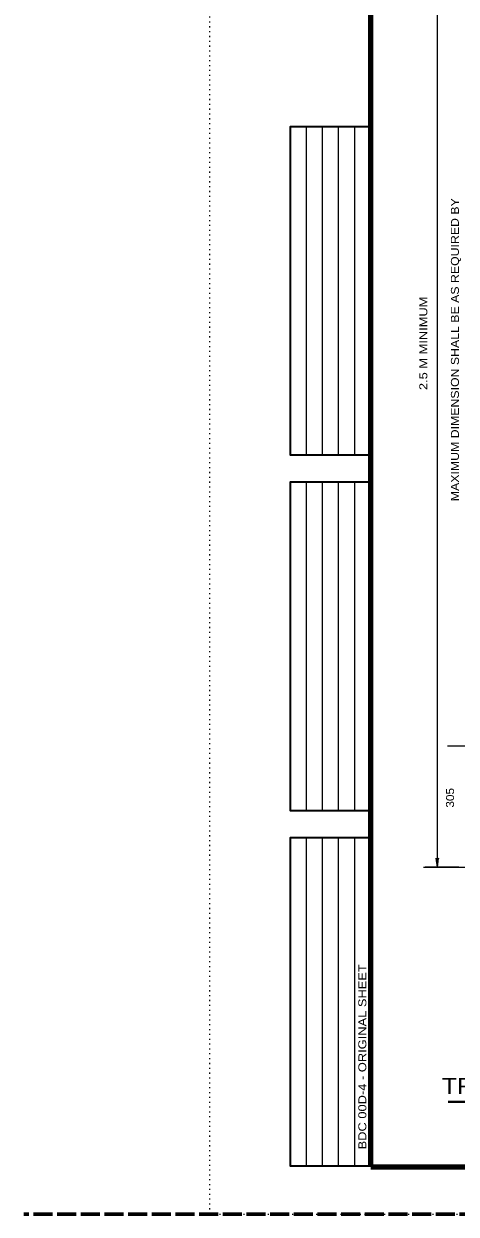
# Model space of a CAD drawing. Extents: x 312583 to 312854, y 144419 to 144597.
# Drawn here: x 312583.5 to 312624.6, y 144418.6 to 144531.6 of the extents above; entities that cross this region are included whole.
import ezdxf
from ezdxf.enums import TextEntityAlignment as Align

# ---------------------------------------------------------------- set-up
doc = ezdxf.new("R2010")
doc.units = 0
doc.header["$LTSCALE"] = 0.3
doc.linetypes.add('DOTTED', pattern=[1.5, 0.3, -1.2])
doc.linetypes.add('LONG_DASHED', pattern=[7.5, 6, -1.5])
for name, color, linetype, lineweight in [('1', 7, 'Continuous', 40), ('2', 7, 'Continuous', 13), ('62', 7, 'DOTTED', 13), ('63', 7, 'LONG_DASHED', 60)]:
    doc.layers.add(name, color=color, linetype=linetype, lineweight=lineweight)

msp = doc.modelspace()

# ---------------------------------------------------------------- linework, layer by layer
at = {"layer": '1', "lineweight": 25}
for p, q in [((312610.4087, 144490.6573), (312610.4087, 144521.8756)), ((312611.9315, 144490.6573), (312611.9315, 144521.8756)), ((312613.4543, 144490.6573), (312613.4543, 144521.8756)), ((312614.9772, 144490.6573), (312614.9772, 144521.8756)), ((312610.4087, 144456.901), (312610.4087, 144488.1192)), ((312611.9315, 144456.901), (312611.9315, 144488.1192)), ((312613.4543, 144456.901), (312613.4543, 144488.1192)), ((312614.9772, 144456.901), (312614.9772, 144488.1192)), ((312610.4087, 144423.1446), (312610.4087, 144454.3629)), ((312611.9315, 144423.1446), (312611.9315, 144454.3629)), ((312613.4543, 144423.1446), (312613.4543, 144454.3629)), ((312614.9772, 144423.1446), (312614.9772, 144454.3629))]:
    msp.add_line(p, q, dxfattribs=at)
at = {"layer": '1', "lineweight": 158}
msp.add_line((312616.5, 144423.0846), (312849, 144423.0846), dxfattribs=at)
msp.add_lwpolyline([(312616.5, 144423.1446), (312616.5, 144585.0846), (312849, 144585.0846)], dxfattribs=at)
at = {"layer": '1', "lineweight": 35}
for points in [[(312616.5, 144490.6573), (312608.8858, 144490.6573), (312608.8858, 144521.8756), (312616.5, 144521.8756)], [(312616.5, 144456.901), (312608.8858, 144456.901), (312608.8858, 144488.1192), (312616.5, 144488.1192)], [(312616.5, 144423.1446), (312608.8858, 144423.1446), (312608.8858, 144454.3629), (312616.5, 144454.3629)]]:
    msp.add_lwpolyline(points, dxfattribs=at)
at = {"layer": '2'}
for p, q in [((312622.8377, 144451.5266), (312622.8377, 144543.4269)), ((312622.7303, 144452.3929), (312622.8377, 144452.1169)), ((312622.8377, 144451.5266), (312622.7303, 144452.3929)), ((312622.945, 144452.3929), (312622.8377, 144452.1169)), ((312622.8377, 144451.5266), (312622.945, 144452.3929)), ((312627.1785, 144451.5113), (312621.5244, 144451.5113)), ((312624.8632, 144451.5266), (312621.6662, 144451.5266))]:
    msp.add_line(p, q, dxfattribs=at)
at = {"layer": '2', "lineweight": 40}
msp.add_line((312655.0296, 144429.2626), (312623.8479, 144429.2626), dxfattribs=at)
at = {"layer": '2'}
msp.add_lwpolyline([(312636.5165, 144463.0419), (312624.8632, 144463.0419), (312623.7925, 144463.0419)], dxfattribs=at)
at = {"layer": '62'}
msp.add_line((312601.2, 144418.5846), (312601.2, 144596.7846), dxfattribs=at)
msp.add_lwpolyline([(312601.2, 144418.5846), (312853.5, 144418.5846), (312853.5, 144596.7846)], dxfattribs=at)
at = {"layer": '63'}
msp.add_line((312851.75, 144418.5846), (312583.526, 144418.5846), dxfattribs=at)

# ---------------------------------------------------------------- texts
at = {"layer": '1', "width": 1.2}
msp.add_text('BDC 00D-4 - ORIGINAL SHEET', height=0.7614, rotation=90, dxfattribs=at).set_placement((312616.0832, 144424.7374))
at = {"layer": '2'}
for s, width, p in [('MAXIMUM DIMENSION SHALL BE AS REQUIRED BY', 1.15, (312624.8845, 144486.2884)), ('2.5 M MINIMUM', 1.2, (312621.8789, 144496.8411)), ('305', 1.1, (312624.4205, 144457.1907))]:
    msp.add_text(s, height=0.76, rotation=90, dxfattribs=dict(at, width=width)).set_placement(p)
at = {"layer": '2', "width": 1.15}
msp.add_text('TRAFFIC SIGNAL PEDESTAL', height=1.52, dxfattribs=at).set_placement((312639.2445, 144430.0062), align=Align.CENTER)

doc.saveas('drawing.dxf')
